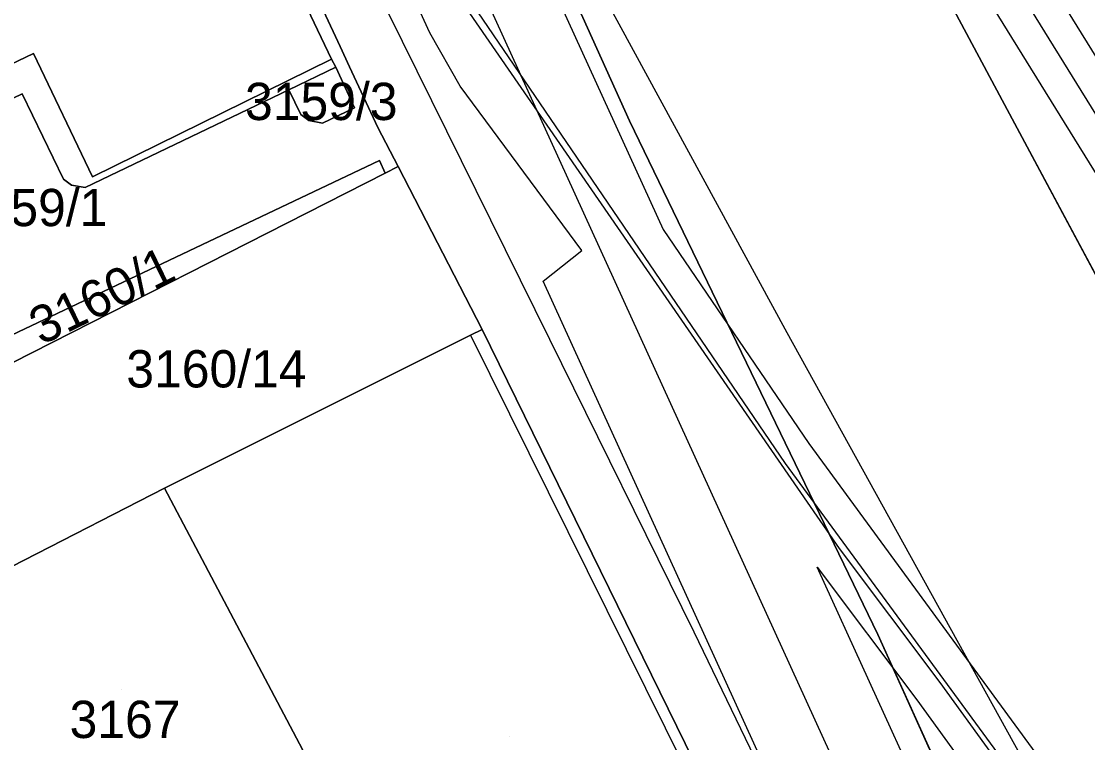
# Model space of a CAD drawing. Extents: x -264070 to -262271, y -1238894 to -1238141.
# Drawn here: x -262970.7 to -262913.5, y -1238505.8 to -1238467.1 of the extents above; entities that cross this region are included whole.
import ezdxf

# ---------------------------------------------------------------- set-up
doc = ezdxf.new("R2010")
doc.units = 0
for name, color, linetype in [('body_kn', 7, 'Continuous'), ('kladpar_druhypozemkov', 7, 'Continuous'), ('kladpar_hranice', 7, 'Continuous'), ('kladpar_parcelnecisla', 7, 'Continuous'), ('kladpar_plochy', 7, 'Continuous'), ('tarchy_linie', 7, 'Continuous'), ('zappar_hrandruhpozemk', 7, 'Continuous')]:
    doc.layers.add(name, color=color, linetype=linetype)

msp = doc.modelspace()

# ---------------------------------------------------------------- linework, layer by layer
at = {"layer": 'body_kn'}
for p, q in [((-262948.78, -1238467.76), (-262948.78, -1238467.76)), ((-262953.6, -1238468.49), (-262953.6, -1238468.49)), ((-262970.05, -1238468.86), (-262970.05, -1238468.86)), ((-262954.06, -1238469.16), (-262954.06, -1238469.16)), ((-262953.83, -1238469.59), (-262953.83, -1238469.59)), ((-262953.83, -1238469.59), (-262953.83, -1238469.59)), ((-262953.1, -1238469.57), (-262953.1, -1238469.57)), ((-262956.35, -1238470.8), (-262956.35, -1238470.8)), ((-262947.17, -1238470.61), (-262947.17, -1238470.61)), ((-262970.65, -1238471.02), (-262970.65, -1238471.02)), ((-262952.82, -1238471.78), (-262952.82, -1238471.78)), ((-262955.71, -1238472.14), (-262955.71, -1238472.14)), ((-262955.28, -1238472.46), (-262955.28, -1238472.46)), ((-262954.55, -1238472.6), (-262954.55, -1238472.6)), ((-262938.08, -1238472.48), (-262938.08, -1238472.48)), ((-262951.58, -1238472.83), (-262951.58, -1238472.83)), ((-262951.58, -1238472.83), (-262951.58, -1238472.83)), ((-262951.49, -1238474.6), (-262951.49, -1238474.6)), ((-262951.18, -1238475.27), (-262951.18, -1238475.27)), ((-262950.49, -1238474.92), (-262950.49, -1238474.92)), ((-262950.49, -1238474.92), (-262950.49, -1238474.92)), ((-262968.44, -1238475.6), (-262968.44, -1238475.6)), ((-262968, -1238475.92), (-262968, -1238475.92)), ((-262966.88, -1238475.48), (-262966.88, -1238475.48)), ((-262967.27, -1238476.05), (-262967.27, -1238476.05)), ((-262936.28, -1238478.3), (-262936.28, -1238478.3)), ((-262940.64, -1238479.43), (-262940.64, -1238479.43)), ((-262942.71, -1238481.07), (-262942.71, -1238481.07)), ((-262946.6, -1238483.96), (-262946.6, -1238483.96)), ((-262946.6, -1238483.96), (-262946.6, -1238483.96)), ((-262945.99, -1238483.66), (-262945.99, -1238483.66)), ((-262929.65, -1238483.83), (-262929.65, -1238483.83)), ((-262929.65, -1238483.83), (-262929.65, -1238483.83)), ((-262942.37, -1238484.18), (-262942.37, -1238484.18)), ((-262928.47, -1238489.78), (-262928.47, -1238489.78)), ((-262929.74, -1238490.84), (-262929.74, -1238490.84)), ((-262963.01, -1238492.17), (-262963.01, -1238492.17)), ((-262963.01, -1238492.17), (-262963.01, -1238492.17)), ((-262926.84, -1238495.4), (-262926.84, -1238495.4)), ((-262928.02, -1238496.41), (-262928.02, -1238496.41)), ((-262934.63, -1238499.88), (-262934.63, -1238499.88)), ((-262924.76, -1238500.02), (-262924.76, -1238500.02)), ((-262921.43, -1238502.6), (-262921.43, -1238502.6)), ((-262922.68, -1238503.52), (-262922.68, -1238503.52)), ((-262922.68, -1238503.52), (-262922.68, -1238503.52))]:
    msp.add_line(p, q, dxfattribs=at)
at = {"layer": 'kladpar_druhypozemkov'}
for p, q in [((-262954.35, -1238471.52), (-262954.35, -1238471.52)), ((-262970.4, -1238476.32), (-262970.4, -1238476.32)), ((-262960.26, -1238485.34), (-262960.26, -1238485.34)), ((-262965.35, -1238502.97), (-262965.35, -1238502.97)), ((-262944.53, -1238505.47), (-262944.53, -1238505.47))]:
    msp.add_line(p, q, dxfattribs=at)
at = {"layer": 'kladpar_hranice'}
for points in [[(-262912.96, -1238299.77), (-262921.54, -1238329.59), (-262928.62, -1238353.76), (-262936.08, -1238387.45), (-262934.99, -1238433.06), (-262931.12, -1238447), (-262910.65, -1238485.29)], [(-262910.65, -1238485.29), (-262931.12, -1238447), (-262934.99, -1238433.06), (-262936.08, -1238387.45), (-262928.62, -1238353.76), (-262921.54, -1238329.59)], [(-263001.91, -1238356.1), (-262980.46, -1238391.76), (-262968.09, -1238412.47), (-262957.85, -1238431.45), (-262958.52, -1238431.77), (-262946.12, -1238456.17), (-262944.09, -1238459.15), (-262938.08, -1238472.48), (-262924.76, -1238500.02), (-262919.42, -1238511.83), (-262907.79, -1238536.85)], [(-262907.79, -1238536.85), (-262919.42, -1238511.83), (-262924.76, -1238500.02), (-262938.08, -1238472.48), (-262944.09, -1238459.15)], [(-262917.94, -1238541.14), (-262922.37, -1238531.58), (-262923.16, -1238530.02), (-262924.5, -1238527.35), (-262926.92, -1238522.53), (-262945.99, -1238483.66), (-262950.49, -1238474.92), (-262951.58, -1238472.83), (-262953.1, -1238469.57), (-262953.6, -1238468.49), (-262957.3, -1238460.54)], [(-262957.3, -1238460.54), (-262953.6, -1238468.49), (-262953.1, -1238469.57), (-262951.58, -1238472.83)], [(-262955.92, -1238465.25), (-262954.06, -1238469.16), (-262966.88, -1238475.48), (-262970.05, -1238468.86), (-262978.99, -1238473.14), (-262975.88, -1238479.62), (-262974.59, -1238482.31), (-262973.61, -1238484.35), (-262985.15, -1238489.83), (-262987.38, -1238485.14), (-262993.76, -1238471.75), (-262987.33, -1238468.68), (-262986.48, -1238468.27), (-262985.45, -1238467.78), (-262984.09, -1238467.13)], [(-262951.58, -1238472.83), (-262950.49, -1238474.92), (-262951.18, -1238475.27), (-262951.49, -1238474.6), (-262971.23, -1238483.97), (-262971.96, -1238483.83), (-262972.26, -1238483.65), (-262972.52, -1238483.35), (-262976.99, -1238474.06), (-262970.65, -1238471.02), (-262968.44, -1238475.6), (-262968, -1238475.92), (-262967.27, -1238476.05), (-262956.35, -1238470.8), (-262955.71, -1238472.14), (-262955.28, -1238472.46), (-262954.55, -1238472.6), (-262952.82, -1238471.78), (-262953.83, -1238469.59), (-262954.06, -1238469.16), (-262955.92, -1238465.25)], [(-262978.99, -1238473.14), (-262970.05, -1238468.86), (-262966.88, -1238475.48), (-262954.06, -1238469.16), (-262953.83, -1238469.59), (-262956.35, -1238470.8), (-262967.27, -1238476.05), (-262968, -1238475.92), (-262968.44, -1238475.6), (-262970.65, -1238471.02), (-262976.99, -1238474.06)], [(-262953.83, -1238469.59), (-262952.82, -1238471.78), (-262954.55, -1238472.6), (-262955.28, -1238472.46), (-262955.71, -1238472.14), (-262956.35, -1238470.8), (-262953.83, -1238469.59)], [(-262971.23, -1238483.97), (-262951.49, -1238474.6), (-262951.18, -1238475.27), (-262973.27, -1238486.5)], [(-262950.49, -1238474.92), (-262945.99, -1238483.66), (-262946.6, -1238483.96), (-262963.01, -1238492.17), (-262978.09, -1238499.9), (-262982.69, -1238502.27), (-262984.06, -1238499.56), (-262985.41, -1238496.89), (-262986.65, -1238494.45), (-262987.11, -1238493.54), (-262973.27, -1238486.5), (-262951.18, -1238475.27), (-262950.49, -1238474.92)], [(-262926.92, -1238522.53), (-262927.36, -1238522.76), (-262935.54, -1238526.28), (-262939.97, -1238515.55), (-262948.41, -1238519.43), (-262953.72, -1238509.79), (-262955.44, -1238506.52), (-262963.01, -1238492.17), (-262946.6, -1238483.96), (-262945.99, -1238483.66), (-262926.92, -1238522.53)], [(-262963.01, -1238492.17), (-262955.44, -1238506.52), (-262969.73, -1238514.26), (-262970.15, -1238514.49), (-262978.09, -1238499.9), (-262963.01, -1238492.17)]]:
    msp.add_lwpolyline(points, dxfattribs=at)
at = {"layer": 'kladpar_plochy'}
for p, q in [((-262931.12, -1238447), (-262910.65, -1238485.29)), ((-262938.08, -1238472.48), (-262944.09, -1238459.15)), ((-262924.76, -1238500.02), (-262938.08, -1238472.48)), ((-262919.42, -1238511.83), (-262924.76, -1238500.02))]:
    msp.add_line(p, q, dxfattribs=at)
for points in [[(-262910.65, -1238485.29), (-262931.12, -1238447), (-262934.99, -1238433.06), (-262936.08, -1238387.45), (-262928.62, -1238353.76), (-262921.54, -1238329.59), (-262912.96, -1238299.77)], [(-262944.09, -1238459.15), (-262938.08, -1238472.48), (-262924.76, -1238500.02), (-262919.42, -1238511.83), (-262907.79, -1238536.85), (-262915.4, -1238540.18), (-262915.61, -1238540.27), (-262917.94, -1238541.14), (-262922.37, -1238531.58), (-262923.16, -1238530.02), (-262924.5, -1238527.35), (-262926.92, -1238522.53), (-262945.99, -1238483.66), (-262950.49, -1238474.92), (-262951.58, -1238472.83), (-262953.1, -1238469.57), (-262953.6, -1238468.49), (-262957.3, -1238460.54)], [(-262957.3, -1238460.54), (-262953.6, -1238468.49), (-262953.1, -1238469.57), (-262951.58, -1238472.83), (-262950.49, -1238474.92), (-262951.18, -1238475.27), (-262951.49, -1238474.6), (-262971.23, -1238483.97), (-262971.96, -1238483.83), (-262972.26, -1238483.65), (-262972.52, -1238483.35), (-262976.99, -1238474.06), (-262970.65, -1238471.02), (-262968.44, -1238475.6), (-262968, -1238475.92), (-262967.27, -1238476.05), (-262956.35, -1238470.8), (-262955.71, -1238472.14), (-262955.28, -1238472.46), (-262954.55, -1238472.6), (-262952.82, -1238471.78), (-262953.83, -1238469.59), (-262954.06, -1238469.16), (-262955.92, -1238465.25)], [(-262955.92, -1238465.25), (-262954.06, -1238469.16), (-262966.88, -1238475.48), (-262970.05, -1238468.86), (-262978.99, -1238473.14), (-262975.88, -1238479.62), (-262974.59, -1238482.31), (-262973.61, -1238484.35), (-262985.15, -1238489.83), (-262987.38, -1238485.14), (-262993.76, -1238471.75), (-262987.33, -1238468.68), (-262986.48, -1238468.27), (-262985.45, -1238467.78), (-262984.09, -1238467.13)], [(-262978.99, -1238473.14), (-262970.05, -1238468.86), (-262966.88, -1238475.48), (-262954.06, -1238469.16), (-262953.83, -1238469.59), (-262956.35, -1238470.8), (-262967.27, -1238476.05), (-262968, -1238475.92), (-262968.44, -1238475.6), (-262970.65, -1238471.02), (-262976.99, -1238474.06)], [(-262971.23, -1238483.97), (-262951.49, -1238474.6), (-262951.18, -1238475.27), (-262973.27, -1238486.5)]]:
    msp.add_lwpolyline(points, dxfattribs=at)
for points in [[(-262953.83, -1238469.59), (-262952.82, -1238471.78), (-262954.55, -1238472.6), (-262955.28, -1238472.46), (-262955.71, -1238472.14), (-262956.35, -1238470.8)], [(-262950.49, -1238474.92), (-262945.99, -1238483.66), (-262946.6, -1238483.96), (-262963.01, -1238492.17), (-262978.09, -1238499.9), (-262982.69, -1238502.27), (-262984.06, -1238499.56), (-262985.41, -1238496.89), (-262986.65, -1238494.45), (-262987.11, -1238493.54), (-262973.27, -1238486.5), (-262951.18, -1238475.27)], [(-262926.92, -1238522.53), (-262927.36, -1238522.76), (-262935.54, -1238526.28), (-262939.97, -1238515.55), (-262948.41, -1238519.43), (-262953.72, -1238509.79), (-262955.44, -1238506.52), (-262963.01, -1238492.17), (-262946.6, -1238483.96), (-262945.99, -1238483.66)], [(-262963.01, -1238492.17), (-262955.44, -1238506.52), (-262969.73, -1238514.26), (-262970.15, -1238514.49), (-262978.09, -1238499.9)]]:
    msp.add_lwpolyline(points, close=True, dxfattribs=at)
at = {"layer": 'tarchy_linie'}
for points in [[(-262892.23, -1238250.77), (-262903.56, -1238282.44), (-262914.22, -1238322.11), (-262925.77, -1238361.47), (-262932, -1238411), (-262933.07, -1238420.81), (-262929.88, -1238445), (-262902, -1238490), (-262879.2, -1238520.11), (-262865.84, -1238538.82), (-262846.84, -1238581.58), (-262829.05, -1238624.25), (-262812.41, -1238667.65), (-262795.14, -1238711.11), (-262786, -1238738.54)], [(-262903.36, -1238490.94), (-262931.47, -1238445.57), (-262934.73, -1238420.82), (-262934.08, -1238414.85), (-262935.48, -1238412.48), (-262935.91, -1238394.66), (-262928.75, -1238358.85), (-262903.34, -1238273.03)], [(-263038.59, -1238278.01), (-263038.81, -1238283.6), (-263023.76, -1238334.4), (-263004.35, -1238368.98), (-262988.5, -1238396.63), (-262970, -1238425.7), (-262949.59, -1238461.67), (-262929.74, -1238490.84), (-262915.64, -1238510.07), (-262911.62, -1238516.37), (-262904.25, -1238532.08), (-262899.49, -1238561.55), (-262883.46, -1238603.14), (-262855.12, -1238679.37), (-262825.32, -1238749.06), (-262831.6, -1238762.46)], [(-263049.81, -1238282.44), (-263016.2, -1238342.64), (-262978.3, -1238405.77), (-262957.24, -1238440.79), (-262909.76, -1238544.87), (-262886.28, -1238607.09), (-262862.09, -1238671.7), (-262834.14, -1238746.5), (-262835.49, -1238761.73)], [(-263055.03, -1238285.01), (-263051.32, -1238292.29), (-263037.9, -1238316.25), (-263024.35, -1238337.09), (-262999.02, -1238379.63), (-262988.72, -1238396.66), (-262981.15, -1238408.68), (-262970.2, -1238425.82), (-262949.94, -1238461.94), (-262926.84, -1238495.4), (-262921.43, -1238502.6), (-262915.89, -1238510.25), (-262914.81, -1238513.45), (-262908.31, -1238550.69), (-262885.94, -1238597.77), (-262863.52, -1238671.22), (-262830.98, -1238762.57)], [(-262900.27, -1238471.46), (-262868.65, -1238532.05), (-262877.87, -1238519.13), (-262900.64, -1238489.06), (-262928.29, -1238444.44), (-262931.41, -1238420.8), (-262931.27, -1238419.55), (-262900.27, -1238471.46)], [(-262954.14, -1238439.16), (-262936.28, -1238478.3), (-262928.47, -1238489.78), (-262914.29, -1238509.13), (-262910.17, -1238515.57)], [(-262911.43, -1238550.37), (-262914.01, -1238548.52), (-262914.89, -1238548.89), (-262915.51, -1238547.31), (-262916.4, -1238545.02), (-262916.75, -1238544.13), (-262916.97, -1238543.57), (-262916.09, -1238543.2), (-262913.89, -1238544.78), (-262913.69, -1238544.7), (-262915.69, -1238540.3), (-262915.61, -1238540.27), (-262916.41, -1238538.73), (-262942.71, -1238481.07), (-262940.64, -1238479.43), (-262947.17, -1238470.61), (-262948.78, -1238467.76), (-262950.68, -1238463.6)], [(-262922.68, -1238503.52), (-262917.28, -1238510.97), (-262916.32, -1238513.83), (-262913.99, -1238527.15), (-262928.02, -1238496.41), (-262922.68, -1238503.52)]]:
    msp.add_lwpolyline(points, dxfattribs=at)
at = {"layer": 'zappar_hrandruhpozemk'}
for p, q in [((-262946, -1238453.75), (-262929.65, -1238483.83)), ((-262946.6, -1238483.96), (-262927.36, -1238522.76)), ((-262929.65, -1238483.83), (-262910.93, -1238517.66))]:
    msp.add_line(p, q, dxfattribs=at)
msp.add_lwpolyline([(-262954.23, -1238460.19), (-262942.37, -1238484.18), (-262934.63, -1238499.88), (-262917.89, -1238534.54)], dxfattribs=at)

# ---------------------------------------------------------------- texts
at = {"layer": 'kladpar_parcelnecisla'}
for s, p in [('3159/3', (-262958.7, -1238472.43)), ('3159/1', (-262974.259, -1238478.12)), ('3160/14', (-262965.066, -1238486.77)), ('3167', (-262968.106, -1238505.57))]:
    msp.add_text(s, height=2, dxfattribs=at).set_placement(p)
msp.add_text('3160/1', height=2, rotation=26, dxfattribs=at).set_placement((-262969.625, -1238484.525))

doc.saveas('drawing.dxf')
